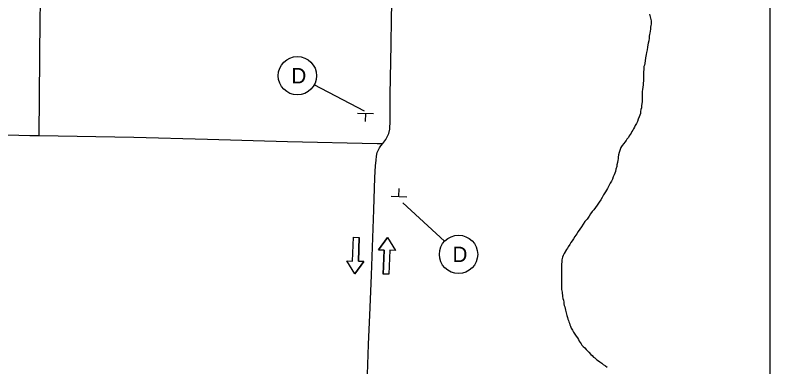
# Model space of a CAD drawing. Extents: x 1633.3 to 1707.6, y 1081.5 to 1106.
# Drawn here: x 1640.38 to 1648.01, y 1090.6 to 1094.16 of the extents above; entities that cross this region are included whole.
import ezdxf

# ---------------------------------------------------------------- set-up
doc = ezdxf.new("R2010")
doc.units = 0
for name, color, linetype in [('GM_X_County_Road', 7, 'Continuous'), ('GM_X_Minor_River', 7, 'Continuous'), ('GM_X_Township_Road', 7, 'Continuous'), ('SH_Data', 7, 'Continuous'), ('SH_Text', 7, 'Continuous'), ('SN_P_Signs', 7, 'Continuous')]:
    doc.layers.add(name, color=color, linetype=linetype)

msp = doc.modelspace()

# ---------------------------------------------------------------- linework, layer by layer
at = {"layer": 'GM_X_County_Road'}
for points in [[(1644.102, 1092.8585), (1644.1321, 1092.8991), (1644.152, 1092.9386), (1644.1601, 1092.9592), (1644.1702, 1093.0024), (1644.1728, 1093.0244), (1644.1756, 1093.0686), (1644.1758, 1093.3536), (1644.1865, 1093.8566), (1644.1891, 1094.1191), (1644.194, 1094.4253), (1644.2086, 1095.1908), (1644.2171, 1095.6502), (1644.2319, 1096.2407), (1644.2313, 1096.3288), (1644.2311, 1096.3693)], [(1643.9071, 1089.384), (1643.9114, 1089.5404), (1643.9273, 1090.0213), (1643.9445, 1090.5242), (1643.9565, 1090.8293), (1643.9741, 1091.2019), (1643.9856, 1091.5297), (1644.0086, 1092.1887), (1644.0208, 1092.5134), (1644.0277, 1092.6341), (1644.0323, 1092.6918), (1644.0369, 1092.7305), (1644.045, 1092.7687), (1644.0543, 1092.7889), (1644.0682, 1092.8156), (1644.0814, 1092.8346), (1644.102, 1092.8585)]]:
    msp.add_lwpolyline(points, dxfattribs=at)
at = {"layer": 'GM_X_Minor_River'}
for points in [[(1646.794, 1094.1645), (1646.7993, 1094.1511), (1646.8019, 1094.1378), (1646.8072, 1094.1244), (1646.8125, 1094.0976), (1646.8125, 1094.0815), (1646.8125, 1094.0628), (1646.8098, 1094.0494), (1646.807, 1094.0334), (1646.8043, 1094.012), (1646.8016, 1093.9933), (1646.7989, 1093.9746), (1646.7962, 1093.9585), (1646.7934, 1093.9425), (1646.7907, 1093.9211), (1646.788, 1093.897), (1646.7826, 1093.8729), (1646.7799, 1093.8542), (1646.7745, 1093.8302), (1646.7717, 1093.8061), (1646.7663, 1093.7767), (1646.7609, 1093.758), (1646.7582, 1093.7393), (1646.7555, 1093.7232), (1646.7473, 1093.667), (1646.7446, 1093.6483), (1646.7392, 1093.635), (1646.7392, 1093.6216), (1646.7365, 1093.6029), (1646.7338, 1093.5868), (1646.7337, 1093.5574), (1646.7336, 1093.536), (1646.7336, 1093.5119), (1646.7336, 1093.4932), (1646.7308, 1093.4691), (1646.7308, 1093.4504), (1646.728, 1093.429), (1646.7253, 1093.4049), (1646.7226, 1093.3835), (1646.7225, 1093.3487), (1646.7225, 1093.3247), (1646.7197, 1093.3033), (1646.7197, 1093.2819), (1646.717, 1093.2605), (1646.7142, 1093.2417), (1646.7142, 1093.2177), (1646.7088, 1093.2016), (1646.7061, 1093.1829), (1646.7034, 1093.1615), (1646.698, 1093.1455), (1646.6926, 1093.1268), (1646.6818, 1093.1027), (1646.6737, 1093.0813), (1646.663, 1093.06), (1646.6522, 1093.0413), (1646.6442, 1093.0226), (1646.6334, 1093.0066), (1646.6254, 1092.9932), (1646.6173, 1092.9799), (1646.6092, 1092.9638), (1646.5905, 1092.9371), (1646.5824, 1092.9184), (1646.5663, 1092.9024), (1646.5582, 1092.8891), (1646.5475, 1092.8731), (1646.5368, 1092.8597), (1646.5207, 1092.8384), (1646.5072, 1092.8197), (1646.4884, 1092.7689), (1646.483, 1092.7449), (1646.4776, 1092.7208), (1646.4775, 1092.7047), (1646.4748, 1092.6887), (1646.4721, 1092.6673), (1646.4667, 1092.6432), (1646.464, 1092.6272), (1646.4559, 1092.6005), (1646.4505, 1092.5764), (1646.4451, 1092.5604), (1646.437, 1092.5417), (1646.429, 1092.5203), (1646.4209, 1092.4989), (1646.4101, 1092.4775), (1646.3994, 1092.4588), (1646.3913, 1092.4428), (1646.3806, 1092.4241), (1646.3698, 1092.4028), (1646.351, 1092.3707), (1646.3322, 1092.3413), (1646.3188, 1092.3146), (1646.3026, 1092.2906), (1646.2866, 1092.2666), (1646.2677, 1092.2372), (1646.249, 1092.2105), (1646.2328, 1092.1892)], [(1646.2328, 1092.1892), (1646.2168, 1092.1705), (1646.2007, 1092.1491), (1646.1845, 1092.1251), (1646.1657, 1092.0931), (1646.1416, 1092.0691), (1646.1255, 1092.0423), (1646.1067, 1092.0183), (1646.0906, 1091.9916), (1646.0745, 1091.9703), (1646.061, 1091.9462), (1646.0423, 1091.9195), (1646.0288, 1091.8955), (1646.0127, 1091.8768), (1646.002, 1091.8581), (1645.9912, 1091.8394), (1645.9751, 1091.8154), (1645.9671, 1091.8021), (1645.9563, 1091.7887), (1645.9322, 1091.7487), (1645.9241, 1091.7273), (1645.916, 1091.7113), (1645.9133, 1091.6979), (1645.9106, 1091.6845), (1645.9079, 1091.6604), (1645.9052, 1091.6444), (1645.9051, 1091.631), (1645.9051, 1091.615), (1645.905, 1091.5989), (1645.905, 1091.5829), (1645.905, 1091.5615), (1645.9049, 1091.5427), (1645.9049, 1091.5213), (1645.9075, 1091.4973), (1645.9074, 1091.4785), (1645.9074, 1091.4544), (1645.9073, 1091.4277), (1645.9073, 1091.4036), (1645.9072, 1091.3849), (1645.9099, 1091.3715), (1645.9125, 1091.3581), (1645.9125, 1091.3447), (1645.9151, 1091.326), (1645.9178, 1091.3126), (1645.9204, 1091.2912), (1645.9257, 1091.2751), (1645.9284, 1091.2564), (1645.931, 1091.2377), (1645.9336, 1091.2216), (1645.9389, 1091.2082), (1645.9416, 1091.1921), (1645.9469, 1091.1761), (1645.9495, 1091.16), (1645.9575, 1091.1359), (1645.9601, 1091.1225), (1645.9654, 1091.1011), (1645.9708, 1091.085), (1645.9761, 1091.0716), (1645.9787, 1091.0556), (1645.9867, 1091.0422), (1645.9894, 1091.0261), (1645.9974, 1091.0127), (1646.0053, 1090.9939), (1646.016, 1090.9725), (1646.0266, 1090.9537), (1646.056, 1090.9109), (1646.0666, 1090.8947), (1646.0773, 1090.8787), (1646.0853, 1090.8626), (1646.096, 1090.8492), (1646.104, 1090.8358), (1646.112, 1090.8224), (1646.1253, 1090.809), (1646.1413, 1090.7929), (1646.1547, 1090.7767), (1646.168, 1090.7633), (1646.1814, 1090.7499), (1646.2027, 1090.7284), (1646.2161, 1090.7177), (1646.2294, 1090.7016), (1646.2428, 1090.6935), (1646.2642, 1090.6747), (1646.2802, 1090.664), (1646.2935, 1090.6532), (1646.3122, 1090.6398), (1646.3283, 1090.6264), (1646.3496, 1090.6129), (1646.3683, 1090.5995)]]:
    msp.add_lwpolyline(points, dxfattribs=at)
at = {"layer": 'GM_X_Township_Road'}
for points in [[(1640.6274, 1092.9386), (1640.6382, 1094.1222), (1640.6435, 1094.4071), (1640.6486, 1094.7139), (1640.6535, 1094.9987), (1640.6576, 1095.2616), (1640.662, 1095.4584), (1640.6703, 1096.1149), (1640.6763, 1096.4886), (1640.6823, 1096.8316), (1640.6858, 1097.2139), (1640.6942, 1097.7609), (1640.6989, 1098.0855), (1640.7049, 1098.5723), (1640.7121, 1098.9202), (1640.7121, 1099.0444), (1640.7157, 1099.0764), (1640.7182, 1099.096), (1640.7312, 1099.1395)], [(1637.0896, 1093.0279), (1637.3644, 1093.0196), (1637.9549, 1093.0061), (1639.4858, 1092.9677), (1639.9669, 1092.956), (1640.5354, 1092.9402), (1640.6274, 1092.9386)], [(1640.6274, 1092.9386), (1641.5852, 1092.9208), (1642.3288, 1092.9019), (1643.1379, 1092.8801), (1644.0428, 1092.8599), (1644.102, 1092.8585)]]:
    msp.add_lwpolyline(points, dxfattribs=at)
at = {"layer": 'SH_Data'}
msp.add_lwpolyline([(1633.3121, 1106.0207), (1648.0121, 1106.0207), (1648.0121, 1086.4207), (1633.3121, 1086.4207)], close=True, dxfattribs=at)
at = {"layer": 'SH_Text'}
for p, q in [((1643.9155, 1093.1854), (1643.408, 1093.4512)), ((1644.3036, 1092.2596), (1644.7249, 1091.8714)), ((1643.7956, 1091.6704), (1643.8046, 1091.9122)), ((1643.8046, 1091.9122), (1643.8625, 1091.9101)), ((1643.8536, 1091.6682), (1643.8625, 1091.9101)), ((1644.1476, 1091.9081), (1644.0581, 1091.7839)), ((1644.1476, 1091.9081), (1644.2276, 1091.7776)), ((1644.0581, 1091.7839), (1644.1127, 1091.7819)), ((1644.1127, 1091.7819), (1644.1038, 1091.54)), ((1644.1707, 1091.7797), (1644.1617, 1091.5378)), ((1644.2276, 1091.7776), (1644.1707, 1091.7797)), ((1643.8187, 1091.5419), (1643.7386, 1091.6725)), ((1643.7386, 1091.6725), (1643.7956, 1091.6704)), ((1643.8187, 1091.5419), (1643.9081, 1091.6662)), ((1643.9081, 1091.6662), (1643.8536, 1091.6682)), ((1644.1617, 1091.5378), (1644.1038, 1091.54))]:
    msp.add_line(p, q, dxfattribs=at)
for points in [[(1644.102, 1092.8585), (1644.1321, 1092.8991), (1644.152, 1092.9386), (1644.1601, 1092.9592), (1644.1702, 1093.0024), (1644.1728, 1093.0244), (1644.1756, 1093.0686), (1644.1758, 1093.3536), (1644.1865, 1093.8566), (1644.1891, 1094.1191), (1644.194, 1094.4253), (1644.2086, 1095.1908), (1644.2171, 1095.6502), (1644.2319, 1096.2407), (1644.2313, 1096.3288), (1644.2311, 1096.3693)], [(1643.9071, 1089.384), (1643.9114, 1089.5404), (1643.9273, 1090.0213), (1643.9445, 1090.5242), (1643.9565, 1090.8293), (1643.9741, 1091.2019), (1643.9856, 1091.5297), (1644.0086, 1092.1887), (1644.0208, 1092.5134), (1644.0277, 1092.6341), (1644.0323, 1092.6918), (1644.0369, 1092.7305), (1644.045, 1092.7687), (1644.0543, 1092.7889), (1644.0682, 1092.8156), (1644.0814, 1092.8346), (1644.102, 1092.8585)]]:
    msp.add_lwpolyline(points, dxfattribs=at)
for points in [[(1643.8625, 1091.9101), (1643.8536, 1091.6682), (1643.9081, 1091.6662), (1643.8187, 1091.5419), (1643.7387, 1091.6725), (1643.7956, 1091.6704), (1643.8046, 1091.9122)], [(1644.1037, 1091.54), (1644.1127, 1091.7819), (1644.0581, 1091.7839), (1644.1476, 1091.9081), (1644.2276, 1091.7776), (1644.1707, 1091.7797), (1644.1617, 1091.5378)]]:
    msp.add_lwpolyline(points, close=True, dxfattribs=at)
for centre in [(1643.2375, 1093.5431), (1644.8657, 1091.7385)]:
    msp.add_circle(centre, 0.1936, dxfattribs=at)
at = {"layer": 'SN_P_Signs'}
for p, q in [((1644.0057, 1093.1581), (1643.8457, 1093.1623)), ((1643.9257, 1093.1602), (1643.9236, 1093.0802)), ((1644.2638, 1092.323), (1644.2659, 1092.4029)), ((1644.1838, 1092.325), (1644.3438, 1092.3209))]:
    msp.add_line(p, q, dxfattribs=at)

# ---------------------------------------------------------------- texts
at = {"layer": 'SH_Text'}
for p in [(1643.1767, 1093.4651), (1644.8049, 1091.6605)]:
    msp.add_text('D', height=0.156, dxfattribs=at).set_placement(p)

doc.saveas('drawing.dxf')
